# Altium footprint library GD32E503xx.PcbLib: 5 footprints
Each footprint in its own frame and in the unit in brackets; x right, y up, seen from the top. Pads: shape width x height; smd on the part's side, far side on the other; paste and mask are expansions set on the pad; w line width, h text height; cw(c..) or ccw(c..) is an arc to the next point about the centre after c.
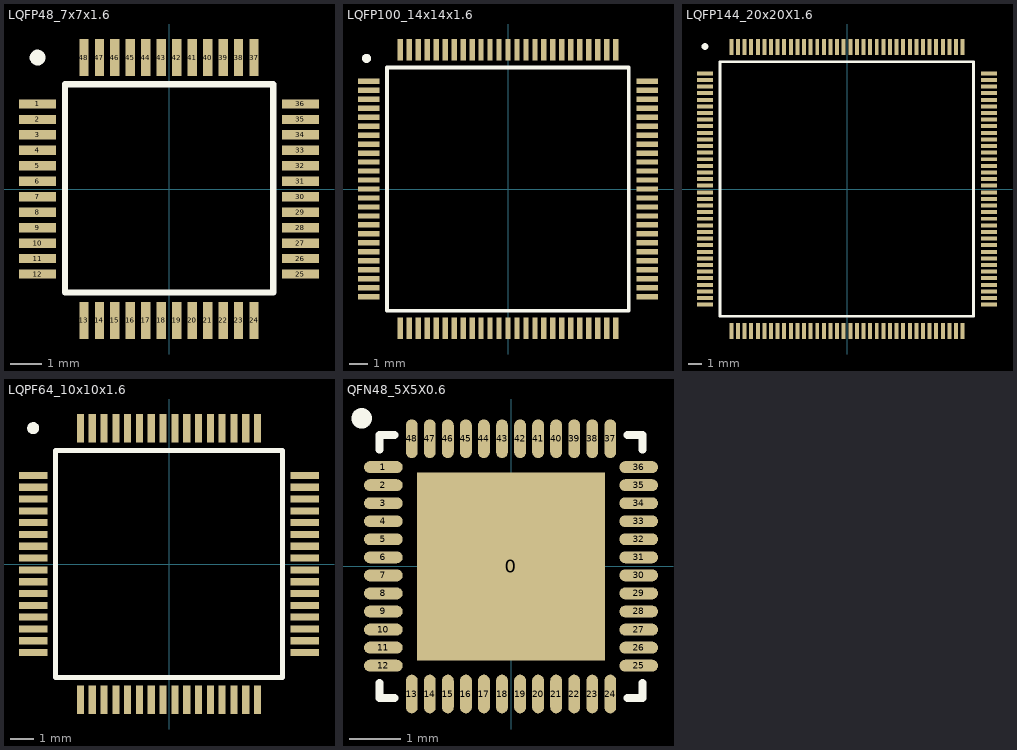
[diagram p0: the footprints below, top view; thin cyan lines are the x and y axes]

## LQFP48_7x7x1.6 [mm]
pads (48):
  rect 1.2x0.3 smd: 1(-4.25,2.75) 2(-4.25,2.25) 3(-4.25,1.75) 4(-4.25,1.25) 5(-4.25,0.75) 6(-4.25,0.25) 7(-4.25,-0.25) 8(-4.25,-0.75) 9(-4.25,-1.25) 10(-4.25,-1.75) 11(-4.25,-2.25) 12(-4.25,-2.75) 25(4.25,-2.75) 26(4.25,-2.25) 27(4.25,-1.75) 28(4.25,-1.25) 29(4.25,-0.75) 30(4.25,-0.25) 31(4.25,0.25) 32(4.25,0.75) 33(4.25,1.25) 34(4.25,1.75) 35(4.25,2.25) 36(4.25,2.75)
  rect 0.3x1.2 smd: 13(-2.75,-4.25) 14(-2.25,-4.25) 15(-1.75,-4.25) 16(-1.25,-4.25) 17(-0.75,-4.25) 18(-0.25,-4.25) 19(0.25,-4.25) 20(0.75,-4.25) 21(1.25,-4.25) 22(1.75,-4.25) 23(2.25,-4.25) 24(2.75,-4.25) 37(2.75,4.25) 38(2.25,4.25) 39(1.75,4.25) 40(1.25,4.25) 41(0.75,4.25) 42(0.25,4.25) 43(-0.25,4.25) 44(-0.75,4.25) 45(-1.25,4.25) 46(-1.75,4.25) 47(-2.25,4.25) 48(-2.75,4.25)
Top Overlay:
  circle w0.254: c-4.25,4.25 r0.127
  lines w0.203: -3.361,-3.346 3.37,-3.346 3.37,3.385 -3.361,3.385 -3.361,-3.346
3D body "TSQFP50P900X900X160-48N.step": height 1.6, standoff 0, extent -4.5,-4.5 4.5,4.5

## LQFP100_14x14x1.6 [mm]
pads (100):
  rect 1.2x0.3 smd: 1(-7.75,6) 2(-7.75,5.5) 3(-7.75,5) 4(-7.75,4.5) 5(-7.75,4) 6(-7.75,3.5) 7(-7.75,3) 8(-7.75,2.5) 9(-7.75,2) 10(-7.75,1.5) 11(-7.75,1) 12(-7.75,0.5) 13(-7.75,0) 14(-7.75,-0.5) 15(-7.75,-1) 16(-7.75,-1.5) 17(-7.75,-2) 18(-7.75,-2.5) 19(-7.75,-3) 20(-7.75,-3.5) 21(-7.75,-4) 22(-7.75,-4.5) 23(-7.75,-5) 24(-7.75,-5.5) 25(-7.75,-6) 51(7.75,-6) 52(7.75,-5.5) 53(7.75,-5) 54(7.75,-4.5) 55(7.75,-4) 56(7.75,-3.5) 57(7.75,-3) 58(7.75,-2.5) 59(7.75,-2) 60(7.75,-1.5) 61(7.75,-1) 62(7.75,-0.5) 63(7.75,0) 64(7.75,0.5) 65(7.75,1) 66(7.75,1.5) 67(7.75,2) 68(7.75,2.5) 69(7.75,3) 70(7.75,3.5) 71(7.75,4) 72(7.75,4.5) 73(7.75,5) 74(7.75,5.5) 75(7.75,6)
  rect 0.3x1.2 smd: 26(-6,-7.75) 27(-5.5,-7.75) 28(-5,-7.75) 29(-4.5,-7.75) 30(-4,-7.75) 31(-3.5,-7.75) 32(-3,-7.75) 33(-2.5,-7.75) 34(-2,-7.75) 35(-1.5,-7.75) 36(-1,-7.75) 37(-0.5,-7.75) 38(0,-7.75) 39(0.5,-7.75) 40(1,-7.75) 41(1.5,-7.75) 42(2,-7.75) 43(2.5,-7.75) 44(3,-7.75) 45(3.5,-7.75) 46(4,-7.75) 47(4.5,-7.75) 48(5,-7.75) 49(5.5,-7.75) 50(6,-7.75) 76(6,7.75) 77(5.5,7.75) 78(5,7.75) 79(4.5,7.75) 80(4,7.75) 81(3.5,7.75) 82(3,7.75) 83(2.5,7.75) 84(2,7.75) 85(1.5,7.75) 86(1,7.75) 87(0.5,7.75) 88(0,7.75) 89(-0.5,7.75) 90(-1,7.75) 91(-1.5,7.75) 92(-2,7.75) 93(-2.5,7.75) 94(-3,7.75) 95(-3.5,7.75) 96(-4,7.75) 97(-4.5,7.75) 98(-5,7.75) 99(-5.5,7.75) 100(-6,7.75)
Top Overlay:
  circle w0.254: c-7.877,7.27 r0.127
  lines w0.203: -6.734,-6.782 6.728,-6.782 6.728,6.762 -6.734,6.762 -6.734,-6.782
3D body "TSQFP50P1600X1600X160-100N.step": height 1.6, standoff 0, extent -8,-8 8,8

## LQFP144_20x20X1.6 [mm]
pads (144):
  rect 1.2x0.3 smd: 1(-10.75,8.75) 2(-10.75,8.25) 3(-10.75,7.75) 4(-10.75,7.25) 5(-10.75,6.75) 6(-10.75,6.25) 7(-10.75,5.75) 8(-10.75,5.25) 9(-10.75,4.75) 10(-10.75,4.25) 11(-10.75,3.75) 12(-10.75,3.25) 13(-10.75,2.75) 14(-10.75,2.25) 15(-10.75,1.75) 16(-10.75,1.25) 17(-10.75,0.75) 18(-10.75,0.25) 19(-10.75,-0.25) 20(-10.75,-0.75) 21(-10.75,-1.25) 22(-10.75,-1.75) 23(-10.75,-2.25) 24(-10.75,-2.75) 25(-10.75,-3.25) 26(-10.75,-3.75) 27(-10.75,-4.25) 28(-10.75,-4.75) 29(-10.75,-5.25) 30(-10.75,-5.75) 31(-10.75,-6.25) 32(-10.75,-6.75) 33(-10.75,-7.25) 34(-10.75,-7.75) 35(-10.75,-8.25) 36(-10.75,-8.75) 73(10.75,-8.75) 74(10.75,-8.25) 75(10.75,-7.75) 76(10.75,-7.25) 77(10.75,-6.75) 78(10.75,-6.25) 79(10.75,-5.75) 80(10.75,-5.25) 81(10.75,-4.75) 82(10.75,-4.25) 83(10.75,-3.75) 84(10.75,-3.25) 85(10.75,-2.75) 86(10.75,-2.25) 87(10.75,-1.75) 88(10.75,-1.25) 89(10.75,-0.75) 90(10.75,-0.25) 91(10.75,0.25) 92(10.75,0.75) 93(10.75,1.25) 94(10.75,1.75) 95(10.75,2.25) 96(10.75,2.75) 97(10.75,3.25) 98(10.75,3.75) 99(10.75,4.25) 100(10.75,4.75) 101(10.75,5.25) 102(10.75,5.75) 103(10.75,6.25) 104(10.75,6.75) 105(10.75,7.25) 106(10.75,7.75) 107(10.75,8.25) 108(10.75,8.75)
  rect 0.3x1.2 smd: 37(-8.75,-10.75) 38(-8.25,-10.75) 39(-7.75,-10.75) 40(-7.25,-10.75) 41(-6.75,-10.75) 42(-6.25,-10.75) 43(-5.75,-10.75) 44(-5.25,-10.75) 45(-4.75,-10.75) 46(-4.25,-10.75) 47(-3.75,-10.75) 48(-3.25,-10.75) 49(-2.75,-10.75) 50(-2.25,-10.75) 51(-1.75,-10.75) 52(-1.25,-10.75) 53(-0.75,-10.75) 54(-0.25,-10.75) 55(0.25,-10.75) 56(0.75,-10.75) 57(1.25,-10.75) 58(1.75,-10.75) 59(2.25,-10.75) 60(2.75,-10.75) 61(3.25,-10.75) 62(3.75,-10.75) 63(4.25,-10.75) 64(4.75,-10.75) 65(5.25,-10.75) 66(5.75,-10.75) 67(6.25,-10.75) 68(6.75,-10.75) 69(7.25,-10.75) 70(7.75,-10.75) 71(8.25,-10.75) 72(8.75,-10.75) 109(8.75,10.75) 110(8.25,10.75) 111(7.75,10.75) 112(7.25,10.75) 113(6.75,10.75) 114(6.25,10.75) 115(5.75,10.75) 116(5.25,10.75) 117(4.75,10.75) 118(4.25,10.75) 119(3.75,10.75) 120(3.25,10.75) 121(2.75,10.75) 122(2.25,10.75) 123(1.75,10.75) 124(1.25,10.75) 125(0.75,10.75) 126(0.25,10.75) 127(-0.25,10.75) 128(-0.75,10.75) 129(-1.25,10.75) 130(-1.75,10.75) 131(-2.25,10.75) 132(-2.75,10.75) 133(-3.25,10.75) 134(-3.75,10.75) 135(-4.25,10.75) 136(-4.75,10.75) 137(-5.25,10.75) 138(-5.75,10.75) 139(-6.25,10.75) 140(-6.75,10.75) 141(-7.25,10.75) 142(-7.75,10.75) 143(-8.25,10.75) 144(-8.75,10.75)
Top Overlay:
  circle w0.254: c-10.75,10.782 r0.127
  lines w0.203: -9.607,-9.627 9.57,-9.627 9.57,9.639 -9.607,9.639 -9.607,-9.627
3D body "TSQFP50P2200X2200X160-144N.step": height 1.6, standoff 0, extent -11,-11 11,11

## LQPF64_10x10x1.6 [mm]
pads (64):
  rect 1.2x0.3 smd: 1(-5.75,3.75) 2(-5.75,3.25) 3(-5.75,2.75) 4(-5.75,2.25) 5(-5.75,1.75) 6(-5.75,1.25) 7(-5.75,0.75) 8(-5.75,0.25) 9(-5.75,-0.25) 10(-5.75,-0.75) 11(-5.75,-1.25) 12(-5.75,-1.75) 13(-5.75,-2.25) 14(-5.75,-2.75) 15(-5.75,-3.25) 16(-5.75,-3.75) 33(5.75,-3.75) 34(5.75,-3.25) 35(5.75,-2.75) 36(5.75,-2.25) 37(5.75,-1.75) 38(5.75,-1.25) 39(5.75,-0.75) 40(5.75,-0.25) 41(5.75,0.25) 42(5.75,0.75) 43(5.75,1.25) 44(5.75,1.75) 45(5.75,2.25) 46(5.75,2.75) 47(5.75,3.25) 48(5.75,3.75)
  rect 0.3x1.2 smd: 17(-3.75,-5.75) 18(-3.25,-5.75) 19(-2.75,-5.75) 20(-2.25,-5.75) 21(-1.75,-5.75) 22(-1.25,-5.75) 23(-0.75,-5.75) 24(-0.25,-5.75) 25(0.25,-5.75) 26(0.75,-5.75) 27(1.25,-5.75) 28(1.75,-5.75) 29(2.25,-5.75) 30(2.75,-5.75) 31(3.25,-5.75) 32(3.75,-5.75) 49(3.75,5.75) 50(3.25,5.75) 51(2.75,5.75) 52(2.25,5.75) 53(1.75,5.75) 54(1.25,5.75) 55(0.75,5.75) 56(0.25,5.75) 57(-0.25,5.75) 58(-0.75,5.75) 59(-1.25,5.75) 60(-1.75,5.75) 61(-2.25,5.75) 62(-2.75,5.75) 63(-3.25,5.75) 64(-3.75,5.75)
Top Overlay:
  circle w0.254: c-5.75,5.75 r0.127
  lines w0.203: -4.801,-4.801 -4.801,4.801 4.801,4.801 4.801,-4.801 -4.801,-4.801
3D body "TSQFP50P1200X1200X160-64N.step": height 1.6, standoff 0, extent -6,-6 6,6

## QFN48_5X5X0.6 [mm]
pads (49):
  rect 3.65x3.65 smd: 0(0,0)
  oval 0.75x0.23 smd: 1(-2.475,1.925) 2(-2.475,1.575) 3(-2.475,1.225) 4(-2.475,0.875) 5(-2.475,0.525) 6(-2.475,0.175) 7(-2.475,-0.175) 8(-2.475,-0.525) 9(-2.475,-0.875) 10(-2.475,-1.225) 11(-2.475,-1.575) 12(-2.475,-1.925) 25(2.475,-1.925) 26(2.475,-1.575) 27(2.475,-1.225) 28(2.475,-0.875) 29(2.475,-0.525) 30(2.475,-0.175) 31(2.475,0.175) 32(2.475,0.525) 33(2.475,0.875) 34(2.475,1.225) 35(2.475,1.575) 36(2.475,1.925)
  oval 0.23x0.75 smd: 13(-1.925,-2.475) 14(-1.575,-2.475) 15(-1.225,-2.475) 16(-0.875,-2.475) 17(-0.525,-2.475) 18(-0.175,-2.475) 19(0.175,-2.475) 20(0.525,-2.475) 21(0.875,-2.475) 22(1.225,-2.475) 23(1.575,-2.475) 24(1.925,-2.475) 37(1.925,2.475) 38(1.575,2.475) 39(1.225,2.475) 40(0.875,2.475) 41(0.525,2.475) 42(0.175,2.475) 43(-0.175,2.475) 44(-0.525,2.475) 45(-0.875,2.475) 46(-1.225,2.475) 47(-1.575,2.475) 48(-1.925,2.475)
Top Overlay:
  circle w0.254: c-2.896,2.87 r0.072
  lines w0.152: -2.551,-2.261 -2.551,-2.551 -2.261,-2.551 ; -2.551,2.261 -2.551,2.551 -2.261,2.551 ; 2.261,-2.551 2.551,-2.551 2.551,-2.261 ; 2.261,2.551 2.551,2.551 2.551,2.261
3D body "QFN35P500X500X60_HS-49N.step": height 0.6, standoff 0, extent -2.551,-2.551 2.551,2.551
